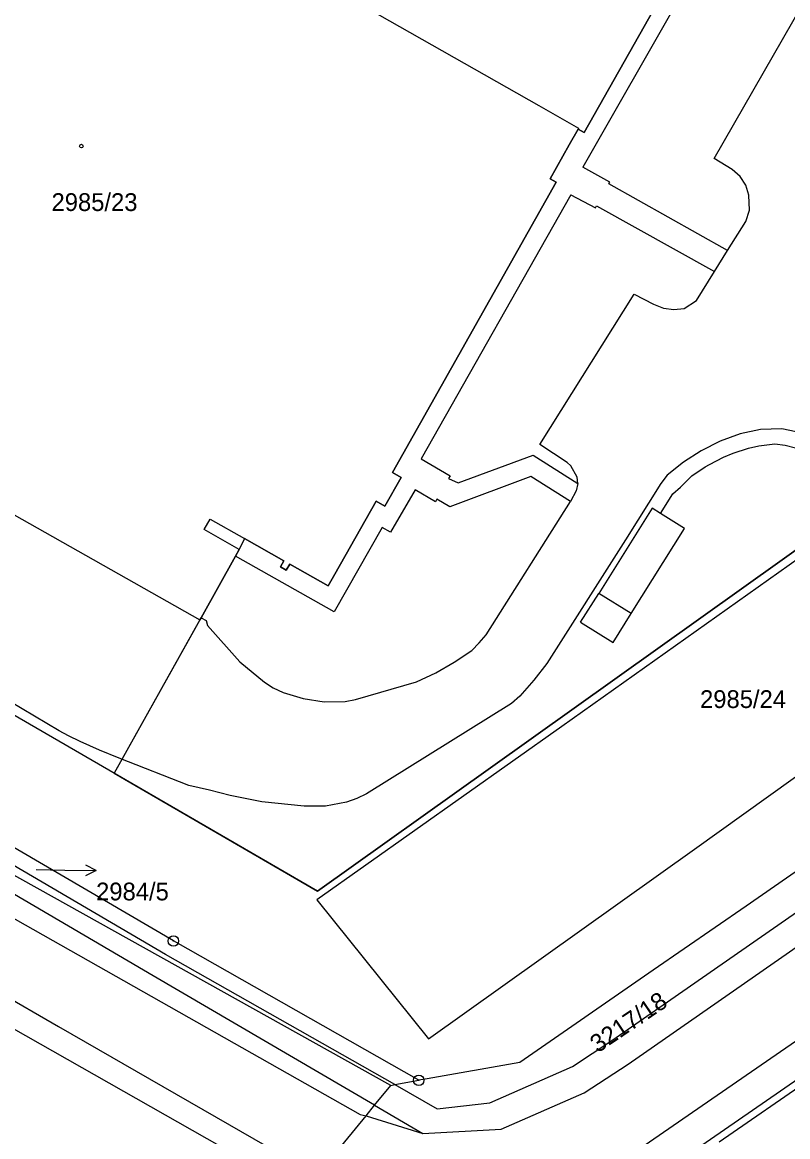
# Model space of a CAD drawing. Extents: x -620475 to -619963, y -1123010 to -1122510.
# Drawn here: x -620107.7 to -620034.5, y -1122851.2 to -1122744.6 of the extents above; entities that cross this region are included whole.
import ezdxf

# ---------------------------------------------------------------- set-up
doc = ezdxf.new("R2010")
doc.units = 0
for name, color, linetype in [('Hranice parcel', 7, 'Continuous'), ('Parcelní čísla', 7, 'Continuous'), ('Pop  PČ popisy', 7, 'Continuous'), ('Vnitřní kresba', 7, 'Continuous'), ('Věcná břemena k části', 7, 'Continuous'), ('Značky bodu BP', 7, 'Continuous'), ('Značky budov', 7, 'Continuous')]:
    doc.layers.add(name, color=color, linetype=linetype)

msp = doc.modelspace()

# ---------------------------------------------------------------- linework, layer by layer
at = {"layer": 'Hranice parcel'}
for p, q in [((-620027.05, -1122841.96), (-620041.07, -1122851.68)), ((-620074.02, -1122848.16), (-620072.47, -1122846.25))]:
    msp.add_line(p, q, dxfattribs=at)
for points in [[(-620129.52, -1122710.96), (-620124.48, -1122713.98), (-620124.94, -1122714.79), (-620058.31, -1122752.59), (-620054.51, -1122754.74), (-620054.56, -1122754.84)], [(-620027.34, -1122787.19), (-620029.12, -1122790.47), (-620030.63, -1122793.23), (-620030.93, -1122793.08), (-620062.93, -1122815.9), (-620079.47, -1122827.69), (-620107.97, -1122811.15), (-620126.88, -1122800.18), (-620134.93, -1122794.41), (-620148.77, -1122775.1), (-620158.3, -1122761.8), (-620160.13, -1122754.62), (-620158.82, -1122744.94), (-620155.87, -1122738.11), (-620144.37, -1122714.62)], [(-620054.56, -1122754.84), (-620053.98, -1122755.17), (-620038.67, -1122728.11), (-620036.56, -1122724.38), (-620035.71, -1122724.86), (-620034.98, -1122723.59)], [(-620122.58, -1122783.75), (-620090.7, -1122801.75), (-620090.59, -1122801.55), (-620087.3, -1122795.66), (-620086.96, -1122795.04), (-620090.3, -1122793.12), (-620089.73, -1122792.12), (-620086.43, -1122793.99), (-620082.68, -1122796.11), (-620083.01, -1122796.68), (-620082.45, -1122797), (-620082.12, -1122796.42), (-620078.46, -1122798.5), (-620077.82, -1122797.38), (-620073.87, -1122790.42), (-620073.02, -1122790.9), (-620071.46, -1122788.15), (-620072.31, -1122787.67), (-620056.64, -1122759.92), (-620057.24, -1122759.58), (-620055.41, -1122756.34), (-620054.56, -1122754.84)], [(-620072.47, -1122846.25), (-620119.48, -1122820.03), (-620130.17, -1122810.08), (-620136, -1122804.68), (-620136.79, -1122803.52), (-620163.81, -1122763.48)], [(-620069.79, -1122845.77), (-620093.24, -1122832.45), (-620114.36, -1122820.1), (-620123.37, -1122813.77), (-620129.15, -1122808.98), (-620134.98, -1122803.58), (-620147.22, -1122786.5), (-620163.81, -1122763.48)], [(-620074.02, -1122848.16), (-620095.17, -1122835.78), (-620116.57, -1122823.25), (-620125.58, -1122816.92), (-620133.3, -1122810.53), (-620139.43, -1122803.84), (-620150.35, -1122788.75), (-620165.02, -1122768.39), (-620166.09, -1122767.67), (-620166.7, -1122767.69)], [(-620030.44, -1122793.73), (-620056.1, -1122811.95), (-620079.53, -1122828.52), (-620068.86, -1122841.8), (-620043.43, -1122823.66), (-620017.73, -1122805.26)], [(-619977.35, -1122803.07), (-619989.26, -1122811.36), (-619995.85, -1122815.89), (-620011.68, -1122826.8), (-620019.22, -1122832.01), (-620044.54, -1122849.47), (-620064.79, -1122863.44), (-620079.86, -1122873.87), (-620081.95, -1122879.05), (-620081.71, -1122879.39)], [(-620080.86, -1122856.55), (-620132.47, -1122827.27), (-620136.72, -1122822.9), (-620143.18, -1122816.17)], [(-620074.02, -1122848.16), (-620069.41, -1122850.86), (-620061.9, -1122850.43), (-620053.99, -1122846.97), (-620049.77, -1122844.23), (-620030.04, -1122830.5), (-620028.57, -1122829.11), (-620027.57, -1122827.35), (-620023.65, -1122820.37), (-620022.03, -1122817.87), (-620021.18, -1122817.07)], [(-620026.52, -1122820.79), (-620038.5, -1122829.12), (-620047.37, -1122835.25), (-620060.13, -1122844.05), (-620068.97, -1122845.62), (-620069.79, -1122845.77)], [(-620072.47, -1122846.25), (-620072.09, -1122846.18), (-620069.79, -1122845.77)], [(-620080.86, -1122856.55), (-620079.9, -1122855.37), (-620074.83, -1122849.15), (-620074.02, -1122848.16)]]:
    msp.add_lwpolyline(points, dxfattribs=at)
at = {"layer": 'Pop  PČ popisy'}
for p, q in [((-620100.63, -1122825.72), (-620101.62, -1122825.2)), ((-620106.35, -1122825.61), (-620103.63, -1122825.67)), ((-620103.63, -1122825.67), (-620100.63, -1122825.72)), ((-620100.63, -1122825.72), (-620101.64, -1122826.21))]:
    msp.add_line(p, q, dxfattribs=at)
at = {"layer": 'Vnitřní kresba'}
for p, q in [((-620035.9, -1122726.57), (-620054.1, -1122758.47)), ((-620041.55, -1122757.64), (-620033.04, -1122742.83)), ((-620039.84, -1122758.71), (-620041.55, -1122757.64)), ((-620051.51, -1122759.9), (-620054.1, -1122758.47)), ((-620039.07, -1122759.38), (-620039.84, -1122758.71)), ((-620051.62, -1122760.07), (-620051.51, -1122759.9)), ((-620040.26, -1122766.46), (-620051.62, -1122760.07)), ((-620038.52, -1122760.2), (-620039.07, -1122759.38)), ((-620038.22, -1122761.15), (-620038.52, -1122760.2)), ((-620055.24, -1122761.12), (-620069.55, -1122786.35)), ((-620055.24, -1122761.12), (-620052.9, -1122762.36)), ((-620038.17, -1122762.58), (-620038.22, -1122761.15)), ((-620052.9, -1122762.36), (-620052.8, -1122762.16)), ((-620052.8, -1122762.16), (-620041.52, -1122768.46)), ((-620038.52, -1122763.67), (-620038.17, -1122762.58)), ((-620040.26, -1122766.46), (-620038.52, -1122763.67)), ((-620041.52, -1122768.46), (-620040.26, -1122766.46)), ((-620043.24, -1122771.24), (-620041.52, -1122768.46)), ((-620058.21, -1122785), (-620049.19, -1122770.62)), ((-620049.19, -1122770.62), (-620047.36, -1122771.58)), ((-620047.36, -1122771.58), (-620046.4, -1122771.95)), ((-620044.41, -1122771.98), (-620043.24, -1122771.24)), ((-620046.4, -1122771.95), (-620045.42, -1122772.1)), ((-620045.42, -1122772.1), (-620044.41, -1122771.98)), ((-620037.11, -1122783.56), (-620039.07, -1122783.97)), ((-620035.08, -1122783.5), (-620037.11, -1122783.56)), ((-620033.11, -1122783.92), (-620035.08, -1122783.5)), ((-620040.98, -1122784.66), (-620042.78, -1122785.58)), ((-620039.07, -1122783.97), (-620040.98, -1122784.66)), ((-620055.6, -1122786.71), (-620058.21, -1122785)), ((-620042.78, -1122785.58), (-620044.47, -1122786.69)), ((-620039.72, -1122785.82), (-620038.28, -1122785.33)), ((-620038.28, -1122785.33), (-620037.29, -1122785.12)), ((-620037.29, -1122785.12), (-620035.74, -1122784.92)), ((-620035.74, -1122784.92), (-620034.76, -1122785.06)), ((-620034.76, -1122785.06), (-620033.77, -1122785.31)), ((-620069.55, -1122786.35), (-620066.78, -1122787.99)), ((-620066.03, -1122788.67), (-620058.85, -1122786.02)), ((-620058.85, -1122786.02), (-620054.57, -1122788.73)), ((-620055.26, -1122787.03), (-620055.6, -1122786.71)), ((-620044.47, -1122786.69), (-620046.04, -1122787.93)), ((-620041.98, -1122786.91), (-620040.65, -1122786.19)), ((-620040.65, -1122786.19), (-620039.72, -1122785.82)), ((-620054.65, -1122788.11), (-620055.26, -1122787.03)), ((-620043.69, -1122788), (-620042.42, -1122787.14)), ((-620042.42, -1122787.14), (-620041.98, -1122786.91)), ((-620066.78, -1122787.99), (-620066.95, -1122788.23)), ((-620066.95, -1122788.23), (-620066.03, -1122788.67)), ((-620059.07, -1122788.06), (-620066.82, -1122790.95)), ((-620055.29, -1122790.43), (-620059.07, -1122788.06)), ((-620054.57, -1122788.73), (-620054.73, -1122789.43)), ((-620054.57, -1122788.73), (-620054.65, -1122788.11)), ((-620046.66, -1122788.71), (-620050.01, -1122794.09)), ((-620046.04, -1122787.93), (-620046.66, -1122788.71)), ((-620044.78, -1122789.08), (-620043.69, -1122788)), ((-620070.13, -1122789.33), (-620072.48, -1122793.37)), ((-620068.2, -1122790.46), (-620070.13, -1122789.33)), ((-620054.73, -1122789.43), (-620055.29, -1122790.43)), ((-620046.67, -1122791.59), (-620045.49, -1122789.69)), ((-620045.49, -1122789.69), (-620044.78, -1122789.08)), ((-620068.05, -1122790.2), (-620068.2, -1122790.46)), ((-620066.82, -1122790.95), (-620068.05, -1122790.2)), ((-620063.35, -1122803.17), (-620055.29, -1122790.43)), ((-620044.39, -1122793.03), (-620046.67, -1122791.59)), ((-620073.28, -1122792.94), (-620077.88, -1122800.99)), ((-620072.48, -1122793.37), (-620073.28, -1122792.94)), ((-620049.47, -1122801.15), (-620044.39, -1122793.03)), ((-620050.01, -1122794.09), (-620057.54, -1122805.91)), ((-620077.88, -1122800.99), (-620087.3, -1122795.66)), ((-620054.32, -1122801.97), (-620052.58, -1122799.22)), ((-620049.47, -1122801.15), (-620052.58, -1122799.22)), ((-620104.17, -1122812.35), (-620119.93, -1122803.03)), ((-620064, -1122803.96), (-620063.35, -1122803.17)), ((-620066.39, -1122805.81), (-620064.71, -1122804.67)), ((-620064.71, -1122804.67), (-620064, -1122803.96)), ((-620086.89, -1122805.77), (-620084.53, -1122807.72)), ((-620068.14, -1122806.82), (-620066.39, -1122805.81)), ((-620057.54, -1122805.91), (-620058.79, -1122807.53)), ((-620069.99, -1122807.67), (-620068.14, -1122806.82)), ((-620084.53, -1122807.72), (-620083.69, -1122808.26)), ((-620075.82, -1122809.38), (-620069.99, -1122807.67)), ((-620058.79, -1122807.53), (-620060.14, -1122809.05)), ((-620083.69, -1122808.26), (-620082.76, -1122808.7)), ((-620082.76, -1122808.7), (-620080.83, -1122809.28)), ((-620060.14, -1122809.05), (-620060.93, -1122809.75)), ((-620080.83, -1122809.28), (-620078.84, -1122809.59)), ((-620078.84, -1122809.59), (-620076.83, -1122809.56)), ((-620076.83, -1122809.56), (-620075.82, -1122809.38)), ((-620060.93, -1122809.75), (-620074.77, -1122818.38)), ((-620103.27, -1122812.85), (-620104.17, -1122812.35)), ((-620102.16, -1122813.38), (-620103.27, -1122812.85)), ((-620100.32, -1122814.22), (-620102.16, -1122813.38)), ((-620098.43, -1122814.97), (-620100.32, -1122814.22)), ((-620091.75, -1122817.59), (-620098.43, -1122814.97)), ((-620089.79, -1122818.03), (-620091.75, -1122817.59)), ((-620087.81, -1122818.54), (-620089.79, -1122818.03)), ((-620084.78, -1122819.14), (-620087.81, -1122818.54)), ((-620074.77, -1122818.38), (-620075.71, -1122818.84)), ((-620127.92, -1122819.29), (-620075.39, -1122849.03)), ((-620080.74, -1122819.56), (-620084.78, -1122819.14)), ((-620078.69, -1122819.55), (-620080.74, -1122819.56)), ((-620076.68, -1122819.17), (-620078.69, -1122819.55)), ((-620075.71, -1122818.84), (-620076.68, -1122819.17)), ((-620093.98, -1122833.75), (-620115.22, -1122821.33)), ((-620129.64, -1122825.94), (-620104.21, -1122840.64)), ((-620051.34, -1122841.97), (-620031.61, -1122828.24)), ((-620015.73, -1122833.37), (-620081.95, -1122879.05)), ((-620072.09, -1122846.18), (-620093.98, -1122833.75)), ((-620104.21, -1122840.64), (-620080.18, -1122854.43)), ((-620055.09, -1122844.45), (-620051.34, -1122841.97)), ((-620063, -1122847.91), (-620055.09, -1122844.45)), ((-620072.09, -1122846.18), (-620068.02, -1122848.49)), ((-620068.02, -1122848.49), (-620063, -1122847.91)), ((-620075.39, -1122849.03), (-620074.83, -1122849.15)), ((-620074.83, -1122849.15), (-620069.41, -1122850.86))]:
    msp.add_line(p, q, dxfattribs=at)
for points in [[(-620046.67, -1122791.59), (-620047.49, -1122791.07), (-620052.58, -1122799.22)], [(-620090.59, -1122801.55), (-620090.11, -1122801.83), (-620089.99, -1122802.28), (-620086.89, -1122805.77)], [(-620054.32, -1122801.97), (-620051.2, -1122803.92), (-620049.47, -1122801.15)]]:
    msp.add_lwpolyline(points, dxfattribs=at)
at = {"layer": 'Věcná břemena k části'}
for points in [[(-620038.67, -1122728.11), (-620053.98, -1122755.17), (-620054.56, -1122754.84), (-620055.41, -1122756.34), (-620057.24, -1122759.58), (-620056.64, -1122759.92), (-620072.31, -1122787.67), (-620071.46, -1122788.15), (-620073.02, -1122790.9), (-620073.87, -1122790.42), (-620077.82, -1122797.38), (-620078.46, -1122798.5), (-620082.12, -1122796.42), (-620082.45, -1122797), (-620083.01, -1122796.68), (-620082.68, -1122796.11), (-620086.43, -1122793.99), (-620086.96, -1122795.04), (-620087.3, -1122795.66), (-620090.59, -1122801.55), (-620090.7, -1122801.75), (-620098.89, -1122816.42), (-620079.47, -1122827.69), (-620062.93, -1122815.9), (-620030.93, -1122793.08)], [(-620038.67, -1122728.11), (-620053.98, -1122755.17), (-620054.56, -1122754.84), (-620055.41, -1122756.34), (-620057.24, -1122759.58), (-620056.64, -1122759.92), (-620072.31, -1122787.67), (-620071.46, -1122788.15), (-620073.02, -1122790.9), (-620073.87, -1122790.42), (-620077.82, -1122797.38), (-620078.46, -1122798.5), (-620082.12, -1122796.42), (-620082.45, -1122797), (-620083.01, -1122796.68), (-620082.68, -1122796.11), (-620086.43, -1122793.99), (-620086.96, -1122795.04), (-620087.3, -1122795.66), (-620098.89, -1122816.42), (-620079.47, -1122827.69), (-620062.93, -1122815.9), (-620030.93, -1122793.08)], [(-620038.67, -1122728.11), (-620053.98, -1122755.17), (-620054.56, -1122754.84), (-620055.41, -1122756.34), (-620057.24, -1122759.58), (-620056.64, -1122759.92), (-620072.31, -1122787.67), (-620071.46, -1122788.15), (-620073.02, -1122790.9), (-620073.87, -1122790.42), (-620077.82, -1122797.38), (-620078.46, -1122798.5), (-620082.12, -1122796.42), (-620082.45, -1122797), (-620083.01, -1122796.68), (-620082.68, -1122796.11), (-620086.43, -1122793.99), (-620086.96, -1122795.04), (-620087.3, -1122795.66), (-620090.59, -1122801.55), (-620090.7, -1122801.75), (-620098.89, -1122816.42), (-620079.47, -1122827.69), (-620062.93, -1122815.9), (-620030.93, -1122793.08)], [(-620038.67, -1122728.11), (-620053.98, -1122755.17), (-620054.56, -1122754.84), (-620055.41, -1122756.34), (-620057.24, -1122759.58), (-620056.64, -1122759.92), (-620072.31, -1122787.67), (-620071.46, -1122788.15), (-620073.02, -1122790.9), (-620073.87, -1122790.42), (-620077.82, -1122797.38), (-620078.46, -1122798.5), (-620082.12, -1122796.42), (-620082.45, -1122797), (-620083.01, -1122796.68), (-620082.68, -1122796.11), (-620086.43, -1122793.99), (-620086.96, -1122795.04), (-620087.3, -1122795.66), (-620090.59, -1122801.55), (-620090.7, -1122801.75), (-620098.89, -1122816.42), (-620079.47, -1122827.69), (-620062.93, -1122815.9), (-620030.93, -1122793.08)]]:
    msp.add_lwpolyline(points, dxfattribs=at)
at = {"layer": 'Značky bodu BP'}
for centre, radius in [((-620093.24, -1122832.45), 0.5), ((-620093.24, -1122832.45), 0.0303), ((-620069.79, -1122845.77), 0.5), ((-620069.79, -1122845.77), 0.0303)]:
    msp.add_circle(centre, radius, dxfattribs=at)
at = {"layer": 'Značky budov'}
msp.add_circle((-620102.04, -1122756.47), 0.175, dxfattribs=at)

# ---------------------------------------------------------------- texts
at = {"layer": 'Parcelní čísla'}
for s, p in [('2985/23', (-620104.89, -1122762.67)), ('2985/24', (-620042.9, -1122810.18)), ('2984/5', (-620100.63, -1122828.57))]:
    msp.add_text(s, height=1.7, dxfattribs=at).set_placement(p)
msp.add_text('3217/18', height=1.7, rotation=34, dxfattribs=at).set_placement((-620052.68, -1122843.2))

doc.saveas('drawing.dxf')
